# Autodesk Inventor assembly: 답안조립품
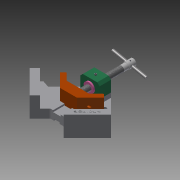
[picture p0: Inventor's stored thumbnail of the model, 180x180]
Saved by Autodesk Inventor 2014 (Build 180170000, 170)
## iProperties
Created: 2019-04
Part Number: 답안조립품
Document SubType Name: Assembly
Designer: kh
Author: kh
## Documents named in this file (11)
- C:\Users\kh\Desktop\490407V1022\답안조립품.iam
- C:\Users\kh\Desktop\490407V1022\본체.ipt
- C:\Users\kh\Desktop\490407V1022\리드스크류.ipt
- C:\Users\kh\Desktop\490407V1022\멈춤나사 M4x5.ipt
- C:\Users\kh\Desktop\490407V1022\멈춤나사 M4x10.ipt
- C:\Users\kh\Desktop\490407V1022\볼트 M4x16.ipt
- C:\Users\kh\Desktop\490407V1022\부시.ipt
- C:\Users\kh\Desktop\490407V1022\서포트.ipt
- C:\Users\kh\Desktop\490407V1022\조.ipt
- C:\Users\kh\Desktop\490407V1022\평행 핀 2.5x24.ipt
- C:\Users\kh\Desktop\490407V1022\핸들.ipt
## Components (1 placed, 1 different names)
1. 핸들:1 — Mate:15, Mate:16, Mate:18, Mate:19, Mate:20, Mate:21, Angle:3
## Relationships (7: Mate 6, Angle 1)
- Mate:15: 핸들:1
- Mate:16: 핸들:1
- Mate:18: 핸들:1
- Mate:19: 핸들:1
- Mate:20: 핸들:1
- Mate:21: 핸들:1
- Angle:3: 핸들:1
